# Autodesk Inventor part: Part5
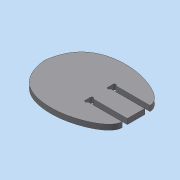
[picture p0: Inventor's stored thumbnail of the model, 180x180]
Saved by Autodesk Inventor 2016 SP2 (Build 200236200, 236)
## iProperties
Created: 2017-07
Part Number: Part5
Material: Generic
Document SubType Name: Modeling
Designer: Mohamed A.
Density: 1 g/cm^3
Appearance: Default
Author: Mohamed A.
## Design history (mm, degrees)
sketch "Sketch1"
  geometry: L1 (0, 0)-(77.079, 0) reference; L2 (77.079, 0)-(77.079, 11) reference; L3 (0, 11)-(77.079, 11) reference; L4 (0, 0)-(0, 11) reference; L5 (77.079, 11)-(77.079, 0) reference; L6 (77.079, 0)-(77.079, -21.454); L7 (77.079, -21.454)-(22.524, -53.918); L8 (22.524, -53.918)-(-21.137, -53.918); L9 (-21.137, -53.918)-(-67.794, -48.883); L10 (-67.794, -48.883)-(-87.025, -14.818); L11 (-87.025, -14.818)-(-91.491, 29.205); L12 (-91.491, 29.205)-(-90.332, 29.205); L13 (-15.219, 0)-(-15.219, 11) reference; L14 (-9.219, 11)-(53.891, 11) reference; L15 (53.891, 11)-(53.891, 28.705) reference; L16 (53.891, 28.705)-(53.891, 46.409) reference; L17 (53.891, 46.409)-(-9.219, 46.409) reference; L18 (-15.219, 46.409)-(-15.219, 57.409) reference; L19 (-9.219, 57.409)-(52.674, 57.409) reference; L20 (52.674, 0)-(-9.219, 0) reference; L21 (80.514, 29.205)-(-147.403, 29.205) reference; L22 (77.079, 11)-(77.079, 29.205); L23 (77.079, 58.409)-(77.079, 79.863); L24 (77.079, 79.863)-(22.524, 112.327); L25 (22.524, 112.327)-(-21.137, 112.327); L26 (-21.137, 112.327)-(-67.794, 107.293); L27 (-67.794, 107.293)-(-87.025, 73.227); L28 (-87.025, 73.227)-(-91.491, 29.205); L29 (-91.491, 29.205)-(-90.332, 29.205); L30 (77.079, 47.409)-(77.079, 29.205); L31 (77.079, 0)-(0, 0) reference; L32 (0, 0)-(0, 11) reference; L33 (77.079, 11)-(0, 11) reference; L34 (77.079, 0)-(77.079, 11) reference; L35 (-88.852, 12)-(-15.047, 12); L36 (-9.219, 11)-(-9.219, 0); L37 (-15.219, 0)-(-86.381, 0); A1 r 3 centre (-12.219, 11) between (-9.219, 11) and (-15.219, 11) reference; A2 r 3 centre (-12.219, 46.409) between (-15.219, 46.409) and (-9.219, 46.409) reference; A3 r 3 centre (-12.219, 57.409) between (-9.219, 57.409) and (-15.219, 57.409) reference; A4 r 3 centre (-12.219, 0) between (-15.219, 0) and (-9.219, 0) reference; 3 further points
  constraints: 14 end point, 7 symmetric about line, 4 horizontal, 3 perpendicular, 2 point on line, 2 vertical, 1 point on circle, 1 vertical alignment, 12 other
extrude "Extrusion1" new body sketch "Sketch1" distance "d4" = 11; taper "d5" = 0 deg
body "Solid1"
node "Reference1"
node "Reference2"
node "Reference3"
